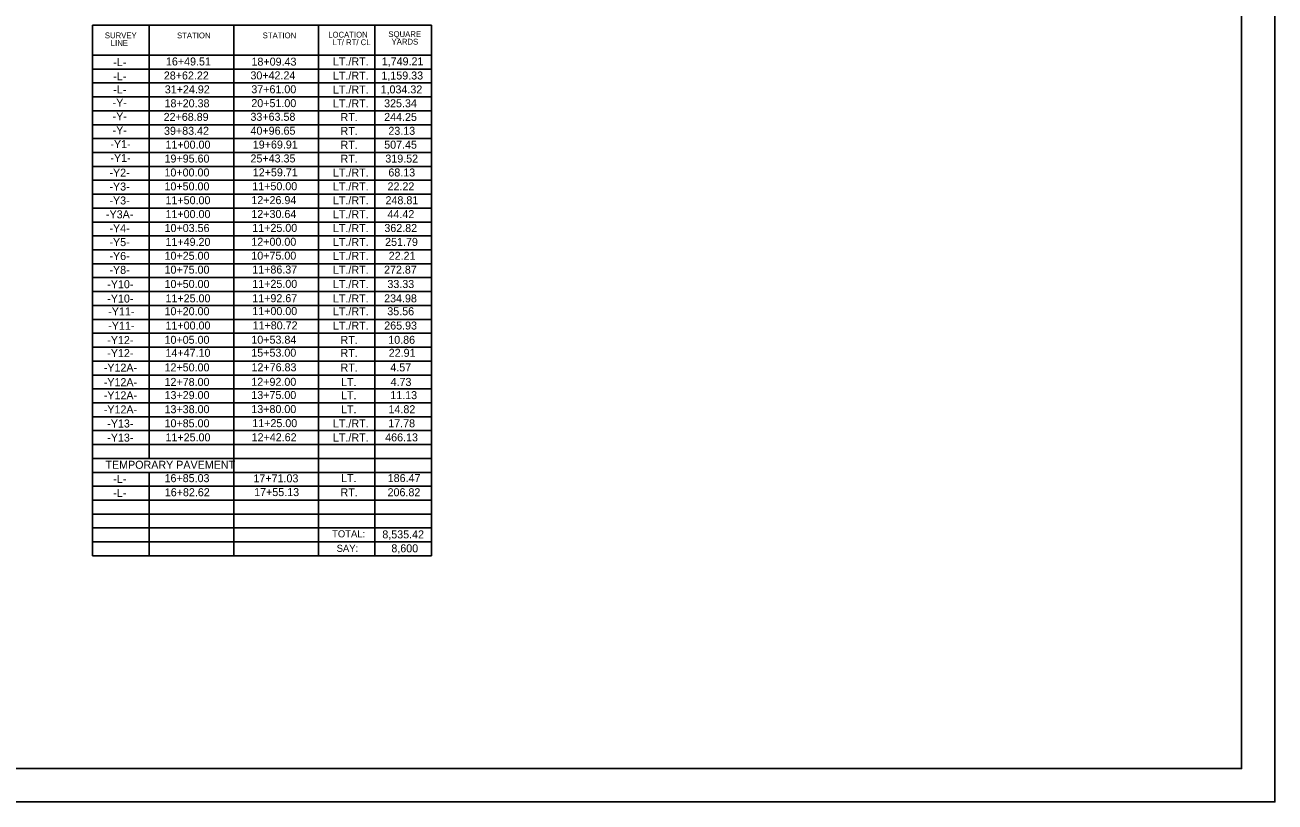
# Model space of a CAD drawing. Extents: x 573680 to 576464, y -53324 to -52224.
# Drawn here: x 574443 to 575380, y -53324 to -52742 of the extents above; entities that cross this region are included whole.
import ezdxf

# ---------------------------------------------------------------- set-up
doc = ezdxf.new("R2010")
doc.units = 0
for name, color, linetype in [('Prop Dimension Text', 7, 'Continuous'), ('Sheet Plan And Profile CELL', 7, 'Continuous'), ('Sheet Plot Border Outside CELL', 7, 'Continuous'), ('Sheet Summary Combination CELL', 7, 'Continuous'), ('Sheet Summary Combination Grid CELL', 7, 'Continuous')]:
    doc.layers.add(name, color=color, linetype=linetype)

msp = doc.modelspace()

# ---------------------------------------------------------------- linework, layer by layer
at = {"layer": 'Sheet Plan And Profile CELL'}
msp.add_lwpolyline([(575354.86, -52249.31), (573854.86, -52249.31), (573854.86, -53299.31), (575354.86, -53299.31)], close=True, dxfattribs=at)
at = {"layer": 'Sheet Plot Border Outside CELL'}
msp.add_lwpolyline([(573679.86, -53324.31), (575379.86, -53324.31), (575379.86, -52224.31), (573679.86, -52224.31)], close=True, dxfattribs=at)
at = {"layer": 'Sheet Summary Combination CELL'}
for p, q in [((574621.25, -52742.02), (574621.25, -52742.02)), ((574626.89, -52742.11), (574626.89, -52742.11)), ((574640.12, -52742.02), (574640.12, -52742.02))]:
    msp.add_line(p, q, dxfattribs=at)
at = {"layer": 'Sheet Summary Combination Grid CELL'}
for p, q in [((574493.78, -52741.98), (574747.69, -52741.98)), ((574493.78, -52741.98), (574493.78, -53139.8)), ((574536.1, -52741.98), (574536.1, -53066.83)), ((574599.59, -52741.98), (574599.59, -53139.8)), ((574663.04, -52741.98), (574663.04, -53139.8)), ((574705.37, -52741.98), (574705.37, -53139.8)), ((574747.69, -52741.98), (574747.69, -53139.8)), ((574493.78, -52764.54), (574747.69, -52764.54)), ((574493.78, -52774.96), (574747.69, -52774.96)), ((574493.78, -52785.39), (574747.69, -52785.39)), ((574493.78, -52795.81), (574747.69, -52795.81)), ((574493.78, -52806.23), (574747.69, -52806.23)), ((574493.78, -52816.66), (574747.69, -52816.66)), ((574493.78, -52827.08), (574747.69, -52827.08)), ((574493.78, -52837.51), (574747.69, -52837.51)), ((574493.78, -52847.93), (574747.69, -52847.93)), ((574493.78, -52858.35), (574747.69, -52858.35)), ((574493.78, -52868.78), (574747.69, -52868.78)), ((574493.78, -52879.2), (574747.69, -52879.2)), ((574493.78, -52889.62), (574747.69, -52889.62)), ((574493.78, -52900.05), (574747.69, -52900.05)), ((574493.78, -52900.05), (574747.69, -52900.05)), ((574493.78, -52900.05), (574747.69, -52900.05)), ((574493.78, -52910.47), (574747.69, -52910.47)), ((574493.78, -52920.9), (574747.69, -52920.9)), ((574493.78, -52931.32), (574747.69, -52931.32)), ((574493.78, -52941.74), (574747.69, -52941.74)), ((574493.78, -52952.17), (574747.69, -52952.17)), ((574493.78, -52962.59), (574747.69, -52962.59)), ((574493.78, -52973.02), (574747.69, -52973.02)), ((574493.78, -52983.44), (574747.69, -52983.44)), ((574493.78, -52993.86), (574747.69, -52993.86)), ((574493.78, -53004.29), (574747.69, -53004.29)), ((574493.78, -53014.71), (574747.69, -53014.71)), ((574493.78, -53025.13), (574747.69, -53025.13)), ((574493.78, -53035.56), (574747.69, -53035.56)), ((574493.78, -53045.98), (574747.69, -53045.98)), ((574493.78, -53056.41), (574747.69, -53056.41)), ((574493.78, -53066.83), (574747.69, -53066.83)), ((574493.78, -53077.25), (574747.69, -53077.25)), ((574536.1, -53077.25), (574536.1, -53139.8)), ((574493.78, -53087.68), (574747.69, -53087.68)), ((574493.78, -53098.1), (574747.69, -53098.1)), ((574493.78, -53108.53), (574747.69, -53108.53)), ((574493.78, -53118.95), (574747.69, -53118.95)), ((574493.78, -53129.37), (574747.69, -53129.37)), ((574493.78, -53139.8), (574747.69, -53139.8))]:
    msp.add_line(p, q, dxfattribs=at)

# ---------------------------------------------------------------- texts
at = {"layer": 'Prop Dimension Text'}
for s, p in [('-L-', (574509.22, -52772.79)), ('16+49.51', (574548.71, -52772.28)), ('18+09.43', (574612.82, -52772.42)), ('LT./RT.', (574673.85, -52772.27)), ('1,749.21', (574710.43, -52772.2)), ('-L-', (574509.22, -52783.35)), ('28+62.22', (574547.12, -52782.8)), ('30+42.24', (574612.01, -52782.71)), ('LT./RT.', (574673.85, -52782.92)), ('1,159.33', (574710.18, -52782.81)), ('-L-', (574509.22, -52793.28)), ('31+24.92', (574547.84, -52793.21)), ('37+61.00', (574612.69, -52793.12)), ('LT./RT.', (574673.85, -52793.33)), ('1,034.32', (574709.56, -52793.22)), ('-Y-', (574508.74, -52803.2)), ('20+51.00', (574612.69, -52803.53)), ('LT./RT.', (574673.85, -52803.74)), ('18+20.38', (574547.65, -52803.62)), ('325.34', (574712.21, -52803.63)), ('-Y-', (574508.74, -52813.43)), ('22+68.89', (574546.98, -52813.85)), ('33+63.58', (574612.02, -52813.76)), ('RT.', (574679.54, -52813.97)), ('244.25', (574712.26, -52813.86)), ('-Y-', (574508.74, -52823.83)), ('39+83.42', (574547.26, -52824.25)), ('40+96.65', (574612.06, -52824.16)), ('RT.', (574679.54, -52824.37)), ('23.13', (574715.39, -52824.26)), ('-Y1-', (574507.08, -52834.23)), ('11+00.00', (574548.36, -52834.65)), ('19+69.91', (574613.79, -52834.56)), ('RT.', (574679.54, -52834.77)), ('507.45', (574712.26, -52834.66)), ('-Y1-', (574507.08, -52844.64)), ('19+95.60', (574547.65, -52845.06)), ('25+43.35', (574612.06, -52844.97)), ('RT.', (574679.54, -52845.17)), ('319.52', (574713.12, -52845.07)), ('-Y2-', (574506.36, -52855.64)), ('10+00.00', (574547.6, -52855.47)), ('12+59.71', (574613.79, -52855.38)), ('LT./RT.', (574673.85, -52855.58)), ('68.13', (574715.39, -52855.48)), ('-Y3-', (574506.36, -52866.04)), ('10+50.00', (574547.6, -52865.87)), ('11+50.00', (574613.4, -52865.78)), ('LT./RT.', (574673.85, -52865.98)), ('22.22', (574714.77, -52865.88)), ('-Y3-', (574506.36, -52876.45)), ('11+50.00', (574548.36, -52876.28)), ('12+26.94', (574612.72, -52876.19)), ('LT./RT.', (574673.85, -52876.39)), ('248.81', (574713.27, -52876.29)), ('-Y3A-', (574503.76, -52886.86)), ('11+00.00', (574548.36, -52886.69)), ('12+30.64', (574612.72, -52886.6)), ('LT./RT.', (574673.85, -52886.8)), ('44.42', (574714.77, -52886.7)), ('10+03.56', (574547.67, -52897.1)), ('11+25.00', (574613.4, -52897.01)), ('LT./RT.', (574673.85, -52897.21)), ('362.82', (574712.4, -52897.11)), ('-Y4-', (574506.36, -52897.27)), ('-Y5-', (574506.36, -52907.68)), ('11+49.20', (574548.36, -52907.51)), ('12+00.00', (574612.69, -52907.42)), ('LT./RT.', (574673.85, -52907.62)), ('251.79', (574712.96, -52907.52)), ('-Y6-', (574506.36, -52918.09)), ('10+25.00', (574547.65, -52917.92)), ('10+75.00', (574612.69, -52917.83)), ('LT./RT.', (574673.85, -52918.03)), ('22.21', (574715.64, -52917.93)), ('-Y8-', (574506.36, -52928.49)), ('10+75.00', (574547.65, -52928.32)), ('11+86.37', (574613.38, -52928.23)), ('LT./RT.', (574673.85, -52928.43)), ('272.87', (574712.14, -52928.33)), ('-Y10-', (574504.71, -52939.24)), ('10+50.00', (574547.65, -52939.06)), ('11+25.00', (574613.4, -52938.97)), ('LT./RT.', (574673.85, -52939.17)), ('33.33', (574714.67, -52939.07)), ('-Y10-', (574504.71, -52949.98)), ('11+25.00', (574548.36, -52949.8)), ('11+92.67', (574613.38, -52949.71)), ('LT./RT.', (574673.85, -52949.92)), ('234.98', (574712.22, -52949.81)), ('-Y11-', (574505.43, -52959.65)), ('10+20.00', (574547.65, -52959.47)), ('11+00.00', (574613.4, -52959.38)), ('LT./RT.', (574673.85, -52959.59)), ('35.56', (574714.6, -52959.48)), ('-Y11-', (574505.43, -52970.37)), ('11+00.00', (574548.36, -52970.19)), ('11+80.72', (574613.64, -52970.1)), ('LT./RT.', (574673.85, -52970.3)), ('265.93', (574712.3, -52970.2)), ('-Y12-', (574504.71, -52981.08)), ('10+05.00', (574547.65, -52980.9)), ('10+53.84', (574612.72, -52980.81)), ('RT.', (574679.54, -52981.02)), ('10.86', (574715.32, -52980.91)), ('-Y12-', (574504.71, -52990.83)), ('14+47.10', (574548.36, -52990.65)), ('15+53.00', (574612.69, -52990.56)), ('RT.', (574679.54, -52990.76)), ('22.91', (574715.64, -52990.66)), ('-Y12A-', (574502.11, -53001.74)), ('12+50.00', (574547.65, -53001.56)), ('12+76.83', (574612.82, -53001.47)), ('RT.', (574679.54, -53001.68)), ('4.57', (574716.89, -53001.57)), ('-Y12A-', (574502.11, -53012.65)), ('12+78.00', (574547.65, -53012.47)), ('12+92.00', (574612.69, -53012.38)), ('LT.', (574679.9, -53012.59)), ('4.73', (574717.05, -53012.48)), ('-Y12A-', (574502.11, -53022.53)), ('13+29.00', (574547.65, -53022.36)), ('13+75.00', (574612.69, -53022.27)), ('LT.', (574679.9, -53022.47)), ('11.13', (574716.83, -53022.37)), ('-Y12A-', (574502.11, -53033.08)), ('13+38.00', (574547.65, -53032.91)), ('13+80.00', (574612.69, -53032.82)), ('LT.', (574679.9, -53033.02)), ('14.82', (574715.49, -53032.92)), ('-Y13-', (574504.71, -53043.63)), ('10+85.00', (574547.65, -53043.46)), ('11+25.00', (574613.4, -53043.37)), ('LT./RT.', (574673.85, -53043.57)), ('17.78', (574715.31, -53043.47)), ('-Y13-', (574504.71, -53054.19)), ('11+25.00', (574548.36, -53054.01)), ('12+42.62', (574612.92, -53053.92)), ('LT./RT.', (574673.85, -53054.12)), ('466.13', (574713.02, -53054.02)), ('TEMPORARY PAVEMENT', (574503.36, -53074.56)), ('186.47', (574714.9, -53084.52)), ('-L-', (574509.22, -53085.11)), ('16+85.03', (574547.65, -53084.6)), ('17+71.03', (574614.26, -53084.74)), ('LT.', (574679.9, -53084.59)), ('-L-', (574509.22, -53095.67)), ('16+82.62', (574547.84, -53095.13)), ('17+55.13', (574614.81, -53095.04)), ('RT.', (574679.54, -53095.24)), ('206.82', (574714.81, -53095.14)), ('8,535.42', (574710.88, -53126.74)), ('8,600', (574717.64, -53137.17))]:
    msp.add_text(s, height=6, dxfattribs=at).set_placement(p)
at = {"layer": 'Sheet Summary Combination CELL'}
for s, height, p in [('SURVEY', 4.332, (574502.93, -52751.89)), ('STATION', 4.332, (574557, -52751.94)), ('STATION', 4.332, (574621.2, -52751.92)), ('LOCATION', 4.332, (574670.31, -52751.37)), ('LINE', 4.332, (574507.36, -52757.58)), ('LT/ RT/ CL', 4.332, (574673.72, -52757.05)), ('TOTAL:', 5.293, (574673.24, -53125.96)), ('SAY:', 5.293, (574676.63, -53136.82))]:
    msp.add_text(s, height=height, dxfattribs=at).set_placement(p)
at = {"layer": 'Sheet Summary Combination Grid CELL'}
for s, p in [('SQUARE', (574715.41, -52750.95)), ('YARDS', (574717.8, -52756.62))]:
    msp.add_text(s, height=4.332, dxfattribs=at).set_placement(p)

doc.saveas('drawing.dxf')
